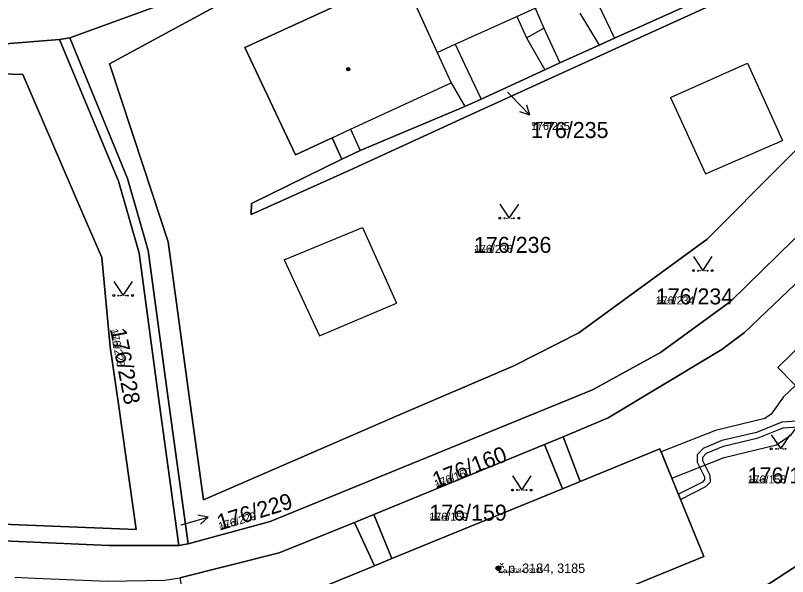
# Model space of a CAD drawing. Extents: x -759873 to -758487, y -975024 to -973516.
# Drawn here: x -759298.9 to -759216.9, y -974841 to -974781.5 of the extents above; entities that cross this region are included whole.
import ezdxf

# ---------------------------------------------------------------- set-up
doc = ezdxf.new("R2010")
doc.units = 0
for name, color, linetype in [('KAT_02_hranice parcel', 7, 'Continuous'), ('KAT_03_1000_čísla parcelní', 7, 'Continuous'), ('KAT_03_1000_čísla popisná', 7, 'Continuous'), ('KAT_03_250_čísla parcelní', 7, 'Continuous'), ('KAT_03_250_čísla popisná', 7, 'Continuous'), ('KAT_03_500_čísla parcelní', 7, 'Continuous'), ('KAT_03_500_čísla popisná', 7, 'Continuous'), ('KAT_04_vnitřní kresba', 7, 'Continuous'), ('KAT_05_1000_značky kultur', 7, 'Continuous'), ('KAT_05_250_značky kultur', 7, 'Continuous'), ('KAT_05_500_značky kultur', 7, 'Continuous'), ('KAT_07_1000_značky budov', 7, 'Continuous'), ('KAT_07_250_značky budov', 7, 'Continuous'), ('KAT_07_500_značky budov', 7, 'Continuous'), ('KAT_10_věcná břemena', 7, 'Continuous'), ('KAT_12_pomocná šipka', 7, 'Continuous'), ('KAT_14_plocha_budovy', 7, 'Continuous'), ('KAT_14_plocha_pozemek', 7, 'Continuous')]:
    doc.layers.add(name, color=color, linetype=linetype)

msp = doc.modelspace()

# ---------------------------------------------------------------- linework, layer by layer
at = {"layer": 'KAT_02_hranice parcel'}
for p, q in [((-759293.14, -974783.84), (-759294.21, -974784.01)), ((-759240.73, -974826.19), (-759242.72, -974826.98)), ((-759242.72, -974826.98), (-759260.85, -974834.41)), ((-759260.85, -974834.41), (-759262.91, -974835.25)), ((-759280.57, -974837.54), (-759281.55, -974837.72))]:
    msp.add_line(p, q, dxfattribs=at)
for points in [[(-759175.88, -974728.64), (-759173.57, -974730.28), (-759172.68, -974733.37), (-759174.3, -974738.51), (-759183.54, -974767.8), (-759185.24, -974771.49), (-759191.6, -974780.57), (-759194.54, -974783.98), (-759207.89, -974797.06), (-759222.97, -974811.82), (-759230.41, -974817.24), (-759237.61, -974821.2), (-759271.85, -974835.17), (-759280.57, -974837.54)], [(-759183.19, -974736.35), (-759176.58, -974737.4), (-759182.07, -974749.11), (-759190.12, -974766.32), (-759202.77, -974781.98), (-759209.13, -974788.81), (-759225.44, -974805.2), (-759239.06, -974815.12), (-759245.96, -974818.65), (-759258.28, -974823.9), (-759278.94, -974832.86), (-759280.49, -974821.62), (-759282.67, -974805.49), (-759285.3, -974797.52), (-759288.93, -974786.59), (-759266.24, -974774.27)], [(-759264.25, -974796.7), (-759273.82, -974801.42), (-759273.86, -974802.58), (-759263.4, -974797.86), (-759250.81, -974792.11), (-759234.75, -974784.78), (-759219.84, -974778), (-759205.42, -974771.5), (-759205, -974770.14), (-759218.68, -974775.94)], [(-759293.14, -974783.84), (-759282.01, -974779.76), (-759267.15, -974772.52)], [(-759266.24, -974774.27), (-759263.84, -974779.97), (-759274.56, -974784.87), (-759269.17, -974796.23), (-759265.28, -974794.44), (-759264.25, -974796.7)], [(-759264.25, -974796.7), (-759262.28, -974795.8), (-759251.19, -974791.13), (-759249.43, -974790.33), (-759242.7, -974787.21), (-759241.08, -974786.49), (-759236.91, -974784.6), (-759235.27, -974783.88), (-759220.2, -974777.07), (-759218.68, -974775.94)], [(-759294.21, -974784.01), (-759302.6, -974784.69), (-759305.68, -974784.73), (-759322.75, -974784.36)], [(-759281.55, -974837.72), (-759283.71, -974821.99), (-759285.78, -974806.67), (-759287.96, -974799.03), (-759294.21, -974784.01)], [(-759280.57, -974837.54), (-759282.72, -974821.86), (-759284.82, -974806.4), (-759287, -974798.76), (-759293.14, -974783.84)], [(-759382.67, -974832.32), (-759358.04, -974833.14), (-759286.08, -974836), (-759287.93, -974822.96), (-759288.84, -974816.61), (-759289.72, -974807.13), (-759291.76, -974802.52), (-759298.13, -974787.72), (-759322.87, -974786.95)], [(-759213.82, -974807.81), (-759221.49, -974815.09), (-759223.9, -974816.9), (-759224.76, -974817.42), (-759235.96, -974824.17), (-759240.73, -974826.19)], [(-759213.82, -974807.81), (-759210.23, -974811.29), (-759217.93, -974818.82), (-759209.28, -974827.66), (-759201.37, -974819.92), (-759196.1, -974825.59)], [(-759231.42, -974847.97), (-759219.46, -974842.13), (-759218.62, -974841.59), (-759204.52, -974832.44), (-759196.1, -974825.59)], [(-759231.42, -974847.97), (-759234, -974842.24), (-759225.78, -974838.87), (-759230.46, -974827.44), (-759238.94, -974830.91), (-759240.73, -974826.19)], [(-759242.72, -974826.98), (-759240.8, -974831.68), (-759250.6, -974835.69), (-759258.94, -974839.1), (-759260.85, -974834.41)], [(-759281.55, -974837.72), (-759288.97, -974837.7), (-759308.21, -974836.87), (-759325.02, -974836.15), (-759358.04, -974834.77), (-759390.43, -974833.42), (-759411.31, -974832.59), (-759418.48, -974833.88), (-759427.06, -974838.9), (-759442.22, -974854.65)], [(-759281.44, -974841.14), (-759270.88, -974838.48), (-759262.91, -974835.25)], [(-759262.91, -974835.25), (-759260.76, -974839.85), (-759270.73, -974843.93), (-759266.05, -974855.36), (-759255.9, -974851.2), (-759253.29, -974857.47)]]:
    msp.add_lwpolyline(points, dxfattribs=at)
at = {"layer": 'KAT_03_1000_čísla popisná'}
msp.add_circle((-759247.62, -974840.12), 0.25, dxfattribs=at)
at = {"layer": 'KAT_03_250_čísla popisná'}
msp.add_circle((-759247.62, -974840.12), 0.0625, dxfattribs=at)
at = {"layer": 'KAT_03_500_čísla popisná'}
msp.add_circle((-759247.62, -974840.12), 0.125, dxfattribs=at)
at = {"layer": 'KAT_04_vnitřní kresba'}
for p, q in [((-759257.83, -974777.22), (-759254.1, -974785.38)), ((-759245.67, -974781.56), (-759243.72, -974780.68)), ((-759243.72, -974780.68), (-759242.8, -974782.82)), ((-759237.07, -974780.19), (-759235.27, -974783.88)), ((-759252.19, -974784.51), (-759245.67, -974781.56)), ((-759245.67, -974781.56), (-759244.64, -974783.84)), ((-759238.96, -974781.21), (-759236.91, -974784.6)), ((-759244.64, -974783.84), (-759242.8, -974782.82)), ((-759242.8, -974782.82), (-759241.08, -974786.49)), ((-759244.64, -974783.84), (-759242.7, -974787.21)), ((-759254.1, -974785.38), (-759252.19, -974784.51)), ((-759252.19, -974784.51), (-759251.19, -974786.68)), ((-759254.1, -974785.38), (-759253.08, -974787.63)), ((-759251.19, -974786.68), (-759249.43, -974790.33)), ((-759229.34, -974790.17), (-759221.16, -974786.53)), ((-759221.16, -974786.53), (-759217.43, -974794.72)), ((-759253.08, -974787.63), (-759252.62, -974788.62)), ((-759263.31, -974793.54), (-759252.62, -974788.62)), ((-759252.62, -974788.62), (-759251.19, -974791.13)), ((-759229.34, -974790.17), (-759225.61, -974798.25)), ((-759265.28, -974794.44), (-759263.31, -974793.54)), ((-759263.31, -974793.54), (-759262.28, -974795.8)), ((-759225.61, -974798.25), (-759217.43, -974794.72)), ((-759270.37, -974807.4), (-759262.04, -974803.97)), ((-759262.04, -974803.97), (-759258.42, -974812)), ((-759270.37, -974807.4), (-759266.62, -974815.44)), ((-759266.62, -974815.44), (-759258.42, -974812)), ((-759240.8, -974831.68), (-759238.94, -974830.91)), ((-759260.76, -974839.85), (-759258.94, -974839.1))]:
    msp.add_line(p, q, dxfattribs=at)
at = {"layer": 'KAT_05_1000_značky kultur'}
for points in [[(-759247.46, -974801.479), (-759246.46, -974802.98), (-759245.46, -974801.479)], [(-759226.91, -974807.039), (-759225.91, -974808.54), (-759224.91, -974807.039)], [(-759288.46, -974809.679), (-759287.46, -974811.18), (-759286.46, -974809.679)], [(-759218.63, -974825.949), (-759217.63, -974827.45), (-759216.63, -974825.949)], [(-759246.13, -974830.319), (-759245.13, -974831.82), (-759244.13, -974830.319)]]:
    msp.add_lwpolyline(points, dxfattribs=at)
for centre in [(-759247.46, -974802.979), (-759245.46, -974802.979), (-759226.91, -974808.539), (-759224.91, -974808.539), (-759288.46, -974811.179), (-759286.46, -974811.179), (-759218.63, -974827.449), (-759246.13, -974831.819), (-759244.13, -974831.819)]:
    msp.add_circle(centre, 0.1, dxfattribs=at)
at = {"layer": 'KAT_05_250_značky kultur'}
for points in [[(-759246.71, -974802.605), (-759246.46, -974802.98), (-759246.21, -974802.605)], [(-759226.16, -974808.165), (-759225.91, -974808.54), (-759225.66, -974808.165)], [(-759287.71, -974810.805), (-759287.46, -974811.18), (-759287.21, -974810.805)], [(-759217.88, -974827.075), (-759217.63, -974827.45), (-759217.38, -974827.075)], [(-759245.38, -974831.445), (-759245.13, -974831.82), (-759244.88, -974831.445)]]:
    msp.add_lwpolyline(points, dxfattribs=at)
for centre in [(-759246.71, -974802.98), (-759246.21, -974802.98), (-759226.16, -974808.54), (-759225.66, -974808.54), (-759287.71, -974811.18), (-759287.21, -974811.18), (-759217.88, -974827.45), (-759217.38, -974827.45), (-759245.38, -974831.82), (-759244.88, -974831.82)]:
    msp.add_circle(centre, 0.025, dxfattribs=at)
at = {"layer": 'KAT_05_500_značky kultur'}
for points in [[(-759246.96, -974802.23), (-759246.46, -974802.98), (-759245.96, -974802.23)], [(-759226.41, -974807.79), (-759225.91, -974808.54), (-759225.41, -974807.79)], [(-759287.96, -974810.429), (-759287.46, -974811.18), (-759286.96, -974810.429)], [(-759218.13, -974826.699), (-759217.63, -974827.45), (-759217.13, -974826.699)], [(-759245.63, -974831.069), (-759245.13, -974831.82), (-759244.63, -974831.069)]]:
    msp.add_lwpolyline(points, dxfattribs=at)
for centre in [(-759246.96, -974802.98), (-759245.96, -974802.98), (-759226.41, -974808.54), (-759225.41, -974808.54), (-759287.96, -974811.18), (-759286.96, -974811.18), (-759218.13, -974827.45), (-759217.13, -974827.45), (-759245.63, -974831.82), (-759244.63, -974831.82)]:
    msp.add_circle(centre, 0.05, dxfattribs=at)
at = {"layer": 'KAT_07_1000_značky budov'}
for centre in [(-759263.557, -974787.169), (-759247.627, -974840.119)]:
    msp.add_circle(centre, 0.175, dxfattribs=at)
at = {"layer": 'KAT_07_250_značky budov'}
for centre in [(-759263.552, -974787.17), (-759247.622, -974840.12)]:
    msp.add_circle(centre, 0.0437, dxfattribs=at)
at = {"layer": 'KAT_07_500_značky budov'}
for centre in [(-759263.553, -974787.17), (-759247.623, -974840.12)]:
    msp.add_circle(centre, 0.0875, dxfattribs=at)
at = {"layer": 'KAT_10_věcná břemena'}
msp.add_lwpolyline([(-759215.04, -974823.9), (-759213.97, -974822.86), (-759216.07, -974820.72), (-759217.32, -974821.94), (-759218.63, -974823.77), (-759219.32, -974824.24), (-759224.54, -974825.51), (-759230.32, -974827.78), (-759229.18, -974830.56), (-759223.64, -974828.37), (-759218.08, -974827.02), (-759216.51, -974825.95)], close=True, dxfattribs=at)
msp.add_lwpolyline([(-759215.35, -974824.49), (-759217.51, -974824.62), (-759220.19, -974825.7), (-759223.9, -974826.58), (-759225.85, -974827.41), (-759226.51, -974828.1), (-759226.52, -974828.86), (-759225.73, -974830.43), (-759225.71, -974830.73), (-759225.94, -974830.98), (-759228.49, -974832.26), (-759228.26, -974832.82), (-759225.58, -974831.46), (-759225.09, -974830.95), (-759225.13, -974830.27), (-759225.92, -974828.72), (-759225.91, -974828.34), (-759225.51, -974827.91), (-759223.72, -974827.16), (-759220.01, -974826.28), (-759217.37, -974825.22), (-759215.27, -974825.09)], dxfattribs=at)
at = {"layer": 'KAT_12_pomocná šipka'}
for p, q in [((-759246.64, -974789.58), (-759246.35, -974789.88)), ((-759246.35, -974789.88), (-759244.265, -974792.039)), ((-759244.265, -974792.039), (-759244.601, -974790.97)), ((-759244.265, -974792.039), (-759245.321, -974791.666)), ((-759281.32, -974835.51), (-759278.435, -974834.683)), ((-759278.435, -974834.683), (-759279.536, -974834.478)), ((-759278.435, -974834.683), (-759279.26, -974835.44)), ((-759281.34, -974835.52), (-759281.32, -974835.51))]:
    msp.add_line(p, q, dxfattribs=at)
at = {"layer": 'KAT_14_plocha_budovy'}
for points in [[(-759247.98, -974768.81), (-759249.96, -974769.71), (-759259.31, -974773.99), (-759257.83, -974777.22), (-759254.1, -974785.38), (-759252.19, -974784.51), (-759245.67, -974781.56), (-759243.72, -974780.68), (-759239.97, -974778.98), (-759238.01, -974778.09), (-759234.02, -974776.29), (-759237.79, -974768.07), (-759239.28, -974764.83), (-759243.41, -974766.72), (-759245.39, -974767.62)], [(-759208.9, -974809.98), (-759210.23, -974811.29), (-759217.93, -974818.82), (-759209.28, -974827.66), (-759201.37, -974819.92), (-759199.92, -974818.5), (-759193.72, -974812.43), (-759185.95, -974804.84), (-759184.5, -974803.41), (-759178.14, -974797.19), (-759186.79, -974788.35), (-759193.36, -974794.78), (-759194.8, -974796.18), (-759202.36, -974803.59)], [(-759270.73, -974843.93), (-759266.05, -974855.36), (-759255.9, -974851.2), (-759253.97, -974850.41), (-759245.92, -974847.12), (-759235.96, -974843.04), (-759234, -974842.24), (-759225.78, -974838.87), (-759230.46, -974827.44), (-759238.94, -974830.91), (-759240.8, -974831.68), (-759250.6, -974835.69), (-759258.94, -974839.1), (-759260.76, -974839.85)]]:
    msp.add_lwpolyline(points, close=True, dxfattribs=at)
at = {"layer": 'KAT_14_plocha_pozemek'}
for points in [[(-759190.12, -974766.32), (-759202.77, -974781.98), (-759209.13, -974788.81), (-759225.44, -974805.2), (-759239.06, -974815.12), (-759245.96, -974818.65), (-759258.28, -974823.9), (-759278.94, -974832.86), (-759280.49, -974821.62), (-759282.67, -974805.49), (-759285.3, -974797.52), (-759288.93, -974786.59), (-759266.24, -974774.27)], [(-759266.24, -974774.27), (-759288.93, -974786.59), (-759285.3, -974797.52), (-759282.67, -974805.49), (-759280.49, -974821.62), (-759278.94, -974832.86), (-759258.28, -974823.9), (-759245.96, -974818.65), (-759239.06, -974815.12), (-759225.44, -974805.2), (-759209.13, -974788.81), (-759202.77, -974781.98), (-759190.12, -974766.32)], [(-759298.96, -974841.08), (-759296.85, -974841.17), (-759289.12, -974841.49), (-759283.04, -974841.37), (-759281.44, -974841.14), (-759270.88, -974838.48), (-759262.91, -974835.25), (-759260.85, -974834.41), (-759242.72, -974826.98), (-759240.73, -974826.19), (-759235.96, -974824.17), (-759224.76, -974817.42), (-759223.9, -974816.9), (-759221.49, -974815.09), (-759213.82, -974807.81), (-759212.35, -974806.39), (-759198.31, -974792.79), (-759196.78, -974791.27), (-759191.81, -974786.42), (-759188.7, -974782.52), (-759182.55, -974773.33)], [(-759263.84, -974779.97), (-759274.56, -974784.87), (-759269.17, -974796.23), (-759265.28, -974794.44), (-759264.25, -974796.7), (-759262.28, -974795.8), (-759251.19, -974791.13), (-759249.43, -974790.33), (-759242.7, -974787.21), (-759241.08, -974786.49), (-759236.91, -974784.6), (-759235.27, -974783.88), (-759220.2, -974777.07)], [(-759219.84, -974778), (-759234.75, -974784.78), (-759250.81, -974792.11), (-759263.4, -974797.86), (-759273.86, -974802.58), (-759273.82, -974801.42), (-759264.25, -974796.7), (-759265.28, -974794.44), (-759269.17, -974796.23), (-759274.56, -974784.87), (-759263.84, -974779.97)], [(-759302.6, -974784.69), (-759294.21, -974784.01), (-759293.14, -974783.84), (-759282.01, -974779.76)], [(-759282.01, -974779.76), (-759293.14, -974783.84), (-759287, -974798.76), (-759284.82, -974806.4), (-759282.72, -974821.86), (-759280.57, -974837.54), (-759271.85, -974835.17), (-759237.61, -974821.2), (-759230.41, -974817.24), (-759222.97, -974811.82), (-759207.89, -974797.06), (-759194.54, -974783.98), (-759191.6, -974780.57)], [(-759191.6, -974780.57), (-759194.54, -974783.98), (-759207.89, -974797.06), (-759222.97, -974811.82), (-759230.41, -974817.24), (-759237.61, -974821.2), (-759271.85, -974835.17), (-759280.57, -974837.54), (-759281.55, -974837.72), (-759288.97, -974837.7), (-759308.21, -974836.87)], [(-759308.21, -974836.87), (-759288.97, -974837.7), (-759281.55, -974837.72), (-759283.71, -974821.99), (-759285.78, -974806.67), (-759287.96, -974799.03), (-759294.21, -974784.01), (-759302.6, -974784.69)], [(-759358.04, -974833.14), (-759286.08, -974836), (-759287.93, -974822.96), (-759288.84, -974816.61), (-759289.72, -974807.13), (-759291.76, -974802.52), (-759298.13, -974787.72), (-759322.87, -974786.95)], [(-759322.87, -974786.95), (-759298.13, -974787.72), (-759291.76, -974802.52), (-759289.72, -974807.13), (-759288.84, -974816.61), (-759287.93, -974822.96), (-759286.08, -974836), (-759358.04, -974833.14)], [(-759171.77, -974799.76), (-759178.71, -974808.89), (-759179.98, -974810.45), (-759194.56, -974824.34), (-759196.1, -974825.59), (-759204.52, -974832.44), (-759218.62, -974841.59), (-759219.46, -974842.13), (-759231.42, -974847.97), (-759233.35, -974848.89), (-759251.38, -974856.67), (-759253.29, -974857.47), (-759264.57, -974861.27), (-759277.27, -974863.6), (-759278.8, -974863.8), (-759286.09, -974864.19), (-759286.94, -974864.24), (-759289.42, -974864.28), (-759298.85, -974863.88), (-759300.86, -974863.82)]]:
    msp.add_lwpolyline(points, dxfattribs=at)
for points in [[(-759205, -974770.14), (-759218.68, -974775.94), (-759220.2, -974777.07), (-759235.27, -974783.88), (-759236.91, -974784.6), (-759241.08, -974786.49), (-759242.7, -974787.21), (-759249.43, -974790.33), (-759251.19, -974791.13), (-759262.28, -974795.8), (-759264.25, -974796.7), (-759273.82, -974801.42), (-759273.86, -974802.58), (-759263.4, -974797.86), (-759250.81, -974792.11), (-759234.75, -974784.78), (-759219.84, -974778), (-759205.42, -974771.5)], [(-759284.82, -974806.4), (-759287, -974798.76), (-759293.14, -974783.84), (-759294.21, -974784.01), (-759287.96, -974799.03), (-759285.78, -974806.67), (-759283.71, -974821.99), (-759281.55, -974837.72), (-759280.57, -974837.54), (-759282.72, -974821.86)], [(-759185.95, -974804.84), (-759179.98, -974810.45), (-759178.71, -974808.89), (-759184.5, -974803.41), (-759178.14, -974797.19), (-759186.79, -974788.35), (-759193.36, -974794.78), (-759196.78, -974791.27), (-759198.31, -974792.79), (-759194.8, -974796.18), (-759202.36, -974803.59), (-759208.9, -974809.98), (-759212.35, -974806.39), (-759213.82, -974807.81), (-759210.23, -974811.29), (-759217.93, -974818.82), (-759209.28, -974827.66), (-759201.37, -974819.92), (-759196.1, -974825.59), (-759194.56, -974824.34), (-759199.92, -974818.5), (-759193.72, -974812.43)], [(-759204.52, -974832.44), (-759196.1, -974825.59), (-759201.37, -974819.92), (-759209.28, -974827.66), (-759217.93, -974818.82), (-759210.23, -974811.29), (-759213.82, -974807.81), (-759221.49, -974815.09), (-759223.9, -974816.9), (-759224.76, -974817.42), (-759235.96, -974824.17), (-759240.73, -974826.19), (-759238.94, -974830.91), (-759230.46, -974827.44), (-759225.78, -974838.87), (-759234, -974842.24), (-759231.42, -974847.97), (-759219.46, -974842.13), (-759218.62, -974841.59)], [(-759253.29, -974857.47), (-759251.38, -974856.67), (-759253.97, -974850.41), (-759245.92, -974847.12), (-759235.96, -974843.04), (-759233.35, -974848.89), (-759231.42, -974847.97), (-759234, -974842.24), (-759225.78, -974838.87), (-759230.46, -974827.44), (-759238.94, -974830.91), (-759240.73, -974826.19), (-759242.72, -974826.98), (-759240.8, -974831.68), (-759250.6, -974835.69), (-759258.94, -974839.1), (-759260.85, -974834.41), (-759262.91, -974835.25), (-759260.76, -974839.85), (-759270.73, -974843.93), (-759266.05, -974855.36), (-759255.9, -974851.2)], [(-759242.72, -974826.98), (-759260.85, -974834.41), (-759258.94, -974839.1), (-759250.6, -974835.69), (-759240.8, -974831.68)], [(-759253.29, -974857.47), (-759255.9, -974851.2), (-759266.05, -974855.36), (-759270.73, -974843.93), (-759260.76, -974839.85), (-759262.91, -974835.25), (-759270.88, -974838.48), (-759281.44, -974841.14), (-759277.27, -974863.6), (-759264.57, -974861.27)]]:
    msp.add_lwpolyline(points, close=True, dxfattribs=at)

# ---------------------------------------------------------------- texts
at = {"layer": 'KAT_03_1000_čísla parcelní'}
for s, p in [('176/235', (-759244.14, -974794.463)), ('176/236', (-759250.2, -974806.65)), ('176/234', (-759230.9, -974812.12)), ('176/158', (-759221.14, -974831.12)), ('176/159', (-759254.94, -974835.07))]:
    msp.add_text(s, height=1.7, dxfattribs=at).set_placement(p)
for s, rotation, p in [('176/228', 281, (-759288.864, -974814.792)), ('176/160', 21, (-759254.225, -974831.643)), ('176/229', 17, (-759277.191, -974836.122))]:
    msp.add_text(s, height=1.7, rotation=rotation, dxfattribs=at).set_placement(p)
at = {"layer": 'KAT_03_1000_čísla popisná'}
msp.add_text('č.p. 3184, 3185', height=1, dxfattribs=at).set_placement((-759247.62, -974840.62))
at = {"layer": 'KAT_03_250_čísla parcelní'}
for s, p in [('176/235', (-759244.14, -974793.188)), ('176/236', (-759250.2, -974806.65)), ('176/234', (-759230.9, -974812.12)), ('176/158', (-759221.14, -974831.12)), ('176/159', (-759254.94, -974835.07))]:
    msp.add_text(s, height=0.425, dxfattribs=at).set_placement(p)
for s, rotation, p in [('176/228', 281, (-759288.864, -974814.792)), ('176/160', 21, (-759254.225, -974831.643)), ('176/229', 17, (-759277.191, -974836.122))]:
    msp.add_text(s, height=0.425, rotation=rotation, dxfattribs=at).set_placement(p)
at = {"layer": 'KAT_03_250_čísla popisná'}
msp.add_text('č.p. 3184, 3185', height=0.25, dxfattribs=at).set_placement((-759247.62, -974840.62))
at = {"layer": 'KAT_03_500_čísla parcelní'}
for s, p in [('176/235', (-759244.14, -974793.613)), ('176/236', (-759250.2, -974806.65)), ('176/234', (-759230.9, -974812.12)), ('176/158', (-759221.14, -974831.12)), ('176/159', (-759254.94, -974835.07))]:
    msp.add_text(s, height=0.85, dxfattribs=at).set_placement(p)
for s, rotation, p in [('176/228', 281, (-759288.864, -974814.792)), ('176/160', 21, (-759254.225, -974831.643)), ('176/229', 17, (-759277.191, -974836.122))]:
    msp.add_text(s, height=0.85, rotation=rotation, dxfattribs=at).set_placement(p)
at = {"layer": 'KAT_03_500_čísla popisná'}
msp.add_text('č.p. 3184, 3185', height=0.5, dxfattribs=at).set_placement((-759247.62, -974840.62))

doc.saveas('drawing.dxf')
